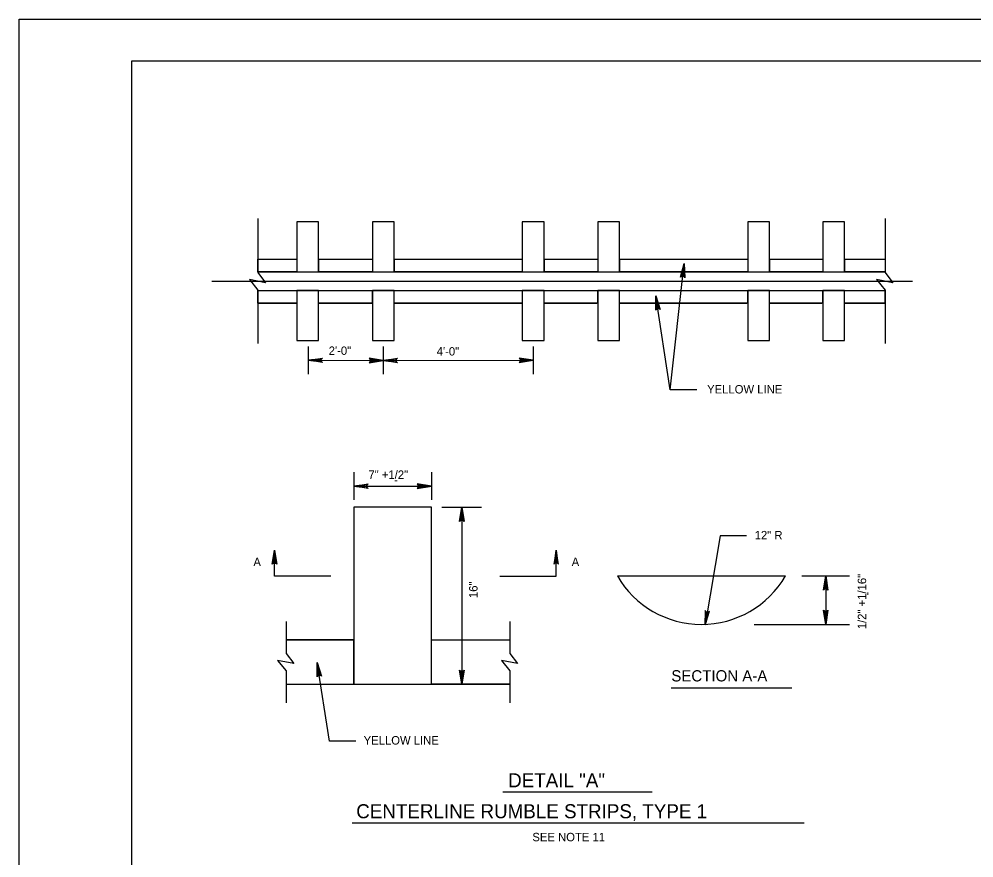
# Model space of a CAD drawing. Extents: x 632008 to 634206, y 294231 to 297795.
# Drawn here: x 632007.9 to 632347.6, y 297496.3 to 297794.6 of the extents above; entities that cross this region are included whole.
import ezdxf

# ---------------------------------------------------------------- set-up
doc = ezdxf.new("R2010")
doc.units = 0
for name, color, linetype in [('1', 7, 'Continuous'), ('Level 2', 7, 'Continuous'), ('PLT-BNDY', 7, 'Continuous')]:
    doc.layers.add(name, color=color, linetype=linetype)

msp = doc.modelspace()

# ---------------------------------------------------------------- linework, layer by layer
at = {"layer": '1'}
for p, q in [((632239.9, 297556.76), (632282.83, 297556.76)), ((632179.98, 297519.79), (632233.04, 297519.79)), ((632126.35, 297508.79), (632287.18, 297508.79))]:
    msp.add_line(p, q, dxfattribs=at)
msp.add_lwpolyline([(632833.86, 297215.62), (632833.86, 297779.62), (632047.86, 297779.62), (632047.86, 297215.62), (632833.86, 297215.62), (632833.86, 297241.98), (632633.86, 297241.98), (632633.86, 297306.66), (632833.86, 297306.66), (632833.86, 297335.62), (632633.86, 297335.62), (632633.86, 297215.62), (632712.66, 297215.62), (632712.66, 297241.98), (632712.66, 297215.62), (632789.66, 297215.62), (632789.66, 297241.98), (632789.66, 297229.66), (632833.86, 297229.66)], dxfattribs=at)
for points in [[(632092.79, 297709.21), (632106.62, 297709.21), (632106.62, 297704.76), (632092.79, 297704.76)], [(632114.46, 297709.21), (632133.54, 297709.21), (632133.54, 297704.76), (632114.46, 297704.76)], [(632141.38, 297709.21), (632186.9, 297709.21), (632186.9, 297704.76), (632141.38, 297704.76)], [(632194.74, 297709.21), (632213.73, 297709.21), (632213.73, 297704.76), (632194.74, 297704.76)], [(632221.57, 297709.21), (632267.09, 297709.21), (632267.09, 297704.76), (632221.57, 297704.76)], [(632274.93, 297709.21), (632293.77, 297709.21), (632293.77, 297704.76), (632274.93, 297704.76)], [(632301.61, 297709.21), (632315.97, 297709.21), (632315.97, 297704.76), (632301.61, 297704.76)], [(632092.79, 297698.09), (632106.62, 297698.09), (632106.62, 297693.64), (632092.79, 297693.64)], [(632114.41, 297698.09), (632133.49, 297698.09), (632133.49, 297693.63), (632114.41, 297693.63)], [(632141.33, 297698.08), (632186.85, 297698.08), (632186.85, 297693.63), (632141.33, 297693.63)], [(632194.69, 297698.08), (632213.68, 297698.08), (632213.68, 297693.63), (632194.69, 297693.63)], [(632221.51, 297698.08), (632267.04, 297698.08), (632267.04, 297693.63), (632221.51, 297693.63)], [(632274.88, 297698.08), (632293.72, 297698.08), (632293.72, 297693.63), (632274.88, 297693.63)], [(632301.56, 297698.08), (632315.92, 297698.08), (632315.92, 297693.63), (632301.56, 297693.63)], [(632127.01, 297573.83), (632102.86, 297573.83), (632102.86, 297569.06), (632105.61, 297565.4), (632099.85, 297566.52), (632102.86, 297562.8), (632102.86, 297558.09), (632127.01, 297558.09)], [(632154.55, 297573.83), (632182.49, 297573.83), (632182.5, 297569.06), (632185.24, 297565.4), (632179.48, 297566.52), (632182.49, 297562.8), (632182.49, 297558.09), (632154.55, 297558.09)]]:
    msp.add_lwpolyline(points, close=True, dxfattribs=at)
at = {"layer": 'Level 2'}
for p, q in [((632092.79, 297723.7), (632092.79, 297704.53)), ((632315.97, 297723.7), (632315.97, 297704.53)), ((632092.79, 297709.21), (632106.64, 297709.21)), ((632092.79, 297709.21), (632106.67, 297709.21)), ((632114.46, 297709.21), (632133.37, 297709.21)), ((632141.38, 297709.21), (632186.75, 297709.21)), ((632194.74, 297709.21), (632213.44, 297709.21)), ((632221.57, 297709.21), (632266.82, 297709.21)), ((632239.52, 297662.73), (632244.5, 297707.74)), ((632274.93, 297709.21), (632293.51, 297709.21)), ((632301.61, 297709.21), (632315.97, 297709.21)), ((632092.79, 297704.76), (632315.97, 297704.76)), ((632092.79, 297704.53), (632095.54, 297700.87)), ((632315.97, 297704.53), (632318.72, 297700.87)), ((632076.4, 297701.42), (632325.68, 297701.42)), ((632095.54, 297700.87), (632089.78, 297701.98)), ((632089.78, 297701.98), (632092.79, 297698.26)), ((632318.72, 297700.87), (632312.96, 297701.98)), ((632312.96, 297701.98), (632315.97, 297698.26)), ((632092.79, 297698.26), (632092.79, 297679.23)), ((632092.79, 297698.09), (632315.97, 297698.09)), ((632315.97, 297698.26), (632315.97, 297679.23)), ((632092.79, 297693.64), (632106.59, 297693.64)), ((632092.79, 297693.64), (632106.62, 297693.64)), ((632114.41, 297693.64), (632133.31, 297693.64)), ((632141.33, 297693.64), (632186.7, 297693.64)), ((632194.69, 297693.64), (632213.39, 297693.64)), ((632221.51, 297693.64), (632266.77, 297693.64)), ((632274.88, 297693.64), (632293.46, 297693.64)), ((632301.56, 297693.64), (632315.97, 297693.64)), ((632110.75, 297678.2), (632110.75, 297668.35)), ((632137.43, 297678.2), (632137.43, 297668.35)), ((632190.79, 297678.2), (632190.79, 297668.35)), ((632110.75, 297673.28), (632137.43, 297673.18)), ((632137.43, 297673.18), (632190.79, 297673.28)), ((632127.01, 297633.48), (632127.01, 297623.62)), ((632154.55, 297633.48), (632154.55, 297623.62)), ((632127.01, 297628.55), (632154.55, 297628.55)), ((632158.31, 297621.04), (632172.43, 297621.04)), ((632165.37, 297621.04), (632165.37, 297558.09)), ((632220.72, 297596.57), (632280.5, 297596.57)), ((632286.37, 297596.57), (632303.28, 297596.57)), ((632294.82, 297596.57), (632294.82, 297579.35)), ((632102.86, 297580.42), (632102.86, 297569.06)), ((632182.5, 297580.42), (632182.5, 297569.06)), ((632269.39, 297579.35), (632303.28, 297579.35)), ((632102.86, 297573.83), (632127.01, 297573.83)), ((632154.55, 297573.83), (632182.5, 297573.83)), ((632102.86, 297569.06), (632105.61, 297565.4)), ((632182.5, 297569.06), (632185.24, 297565.4)), ((632105.61, 297565.4), (632099.85, 297566.52)), ((632099.85, 297566.52), (632102.86, 297562.8)), ((632185.24, 297565.4), (632179.48, 297566.52)), ((632179.48, 297566.52), (632182.49, 297562.8)), ((632102.86, 297562.8), (632102.86, 297551.44)), ((632182.49, 297562.8), (632182.5, 297551.44)), ((632102.86, 297558.09), (632182.49, 297558.09))]:
    msp.add_line(p, q, dxfattribs=at)
for points in [[(632106.62, 297704.76), (632114.41, 297704.76), (632114.41, 297722.55), (632106.62, 297722.55)], [(632133.54, 297704.76), (632141.33, 297704.76), (632141.33, 297722.55), (632133.54, 297722.55)], [(632186.9, 297704.76), (632194.69, 297704.76), (632194.69, 297722.55), (632186.9, 297722.55)], [(632213.73, 297704.76), (632221.51, 297704.76), (632221.51, 297722.55), (632213.73, 297722.55)], [(632267.09, 297704.76), (632274.88, 297704.76), (632274.88, 297722.55), (632267.09, 297722.55)], [(632293.77, 297704.76), (632301.56, 297704.76), (632301.56, 297722.55), (632293.77, 297722.55)], [(632106.62, 297680.29), (632114.41, 297680.29), (632114.41, 297698.09), (632106.62, 297698.09)], [(632133.54, 297680.29), (632141.33, 297680.29), (632141.33, 297698.08), (632133.54, 297698.08)], [(632186.9, 297680.29), (632194.69, 297680.29), (632194.69, 297698.08), (632186.9, 297698.08)], [(632213.73, 297680.29), (632221.51, 297680.29), (632221.51, 297698.08), (632213.73, 297698.08)], [(632267.09, 297680.29), (632274.88, 297680.29), (632274.88, 297698.08), (632267.09, 297698.08)], [(632293.77, 297680.29), (632301.56, 297680.29), (632301.56, 297698.08), (632293.77, 297698.08)], [(632127.01, 297558.09), (632154.55, 297558.09), (632154.55, 297621.04), (632127.01, 297621.04)]]:
    msp.add_lwpolyline(points, close=True, dxfattribs=at)
for points in [[(632243.38, 297703.04), (632243.75, 297703.18), (632244.5, 297707.74), (632243.38, 297703.04), (632243.14, 297702.82), (632244.5, 297707.74), (632244.23, 297703.13), (632244.55, 297702.92), (632244.5, 297707.74), (632244.75, 297702.64), (632244.55, 297702.92)], [(632234.53, 297691.37), (632234.84, 297691.6), (632234.38, 297696.2), (632234.53, 297691.37), (632234.36, 297691.09), (632234.38, 297696.2), (632235.32, 297691.68), (632235.68, 297691.56), (632234.38, 297696.2), (632235.95, 297691.34), (632235.68, 297691.56)], [(632248.94, 297662.73), (632239.52, 297662.73), (632234.38, 297696.2)], [(632115.55, 297672.68), (632115.37, 297673.02), (632110.75, 297673.28), (632115.55, 297672.68), (632115.79, 297672.47), (632110.75, 297673.28), (632115.37, 297673.51), (632115.53, 297673.85), (632110.75, 297673.28), (632115.79, 297674.08), (632115.53, 297673.85)], [(632132.64, 297672.58), (632132.82, 297672.93), (632137.43, 297673.18), (632132.64, 297672.58), (632132.39, 297672.37), (632137.43, 297673.18), (632132.82, 297673.41), (632132.65, 297673.75), (632137.43, 297673.18), (632132.39, 297673.98), (632132.65, 297673.75)], [(632142.23, 297672.58), (632142.05, 297672.93), (632137.43, 297673.18), (632142.23, 297672.58), (632142.47, 297672.37), (632137.43, 297673.18), (632142.05, 297673.41), (632142.22, 297673.75), (632137.43, 297673.18), (632142.47, 297673.98), (632142.22, 297673.75)], [(632186, 297672.68), (632186.18, 297673.02), (632190.79, 297673.28), (632186, 297672.68), (632185.75, 297672.47), (632190.79, 297673.28), (632186.18, 297673.51), (632186.01, 297673.85), (632190.79, 297673.28), (632185.75, 297674.08), (632186.01, 297673.85)], [(632131.81, 297627.95), (632131.63, 297628.29), (632127.01, 297628.55), (632131.81, 297627.95), (632132.06, 297627.74), (632127.01, 297628.55), (632131.63, 297628.78), (632131.8, 297629.12), (632127.01, 297628.55), (632132.06, 297629.35), (632131.8, 297629.12)], [(632149.76, 297627.95), (632149.93, 297628.29), (632154.55, 297628.55), (632149.76, 297627.95), (632149.51, 297627.74), (632154.55, 297628.55), (632149.94, 297628.78), (632149.77, 297629.12), (632154.55, 297628.55), (632149.51, 297629.35), (632149.77, 297629.12)], [(632164.77, 297616.24), (632165.12, 297616.42), (632165.37, 297621.04), (632164.77, 297616.24), (632164.56, 297616), (632165.37, 297621.04), (632165.6, 297616.42), (632165.94, 297616.26), (632165.37, 297621.04), (632166.17, 297616), (632165.94, 297616.26)], [(632266.64, 297610.9), (632257.23, 297610.9), (632251.93, 297579.2)], [(632098.13, 297600.97), (632098.48, 297601.15), (632098.74, 297605.77), (632098.13, 297600.97), (632097.93, 297600.72), (632098.74, 297605.77), (632098.97, 297601.15), (632099.31, 297600.98), (632098.74, 297605.77), (632099.54, 297600.72), (632099.31, 297600.98)], [(632118.82, 297596.56), (632098.74, 297596.56), (632098.74, 297605.77)], [(632178.87, 297596.56), (632198.95, 297596.56), (632198.95, 297605.77)], [(632199.56, 297600.97), (632199.21, 297601.15), (632198.95, 297605.77), (632199.56, 297600.97), (632199.77, 297600.72), (632198.95, 297605.77), (632198.73, 297601.15), (632198.38, 297600.98), (632198.95, 297605.77), (632198.15, 297600.72), (632198.38, 297600.98)], [(632294.22, 297591.77), (632294.57, 297591.95), (632294.82, 297596.57), (632294.22, 297591.77), (632294.01, 297591.53), (632294.82, 297596.57), (632295.05, 297591.96), (632295.39, 297591.79), (632294.82, 297596.57), (632295.62, 297591.53), (632295.39, 297591.79)], [(632252.09, 297584.02), (632252.4, 297583.8), (632251.93, 297579.2), (632252.09, 297584.02), (632251.92, 297584.3), (632251.93, 297579.2), (632252.88, 297583.71), (632253.24, 297583.83), (632251.93, 297579.2), (632253.51, 297584.05), (632253.24, 297583.83)], [(632295.42, 297584.15), (632295.08, 297583.97), (632294.82, 297579.35), (632295.42, 297584.15), (632295.63, 297584.39), (632294.82, 297579.35), (632294.59, 297583.97), (632294.25, 297584.13), (632294.82, 297579.35), (632294.02, 297584.39), (632294.25, 297584.13)], [(632114.08, 297560.98), (632114.39, 297561.21), (632113.93, 297565.81), (632114.08, 297560.98), (632113.91, 297560.7), (632113.93, 297565.81), (632114.87, 297561.29), (632115.23, 297561.17), (632113.93, 297565.81), (632115.5, 297560.95), (632115.23, 297561.17)], [(632127.65, 297537.78), (632118.24, 297537.78), (632113.93, 297565.81)], [(632165.97, 297562.89), (632165.63, 297562.71), (632165.37, 297558.09), (632165.97, 297562.89), (632166.18, 297563.13), (632165.37, 297558.09), (632165.14, 297562.71), (632164.8, 297562.87), (632165.37, 297558.09), (632164.57, 297563.13), (632164.8, 297562.87)]]:
    msp.add_lwpolyline(points, dxfattribs=at)
msp.add_arc((632250.61, 297613.91), 34.56, 210.1174, 329.8826, dxfattribs=at)
at = {"layer": 'PLT-BNDY'}
msp.add_lwpolyline([(632007.86, 297794.62), (632848.86, 297794.62), (632848.86, 297200.62), (632007.86, 297200.62)], close=True, dxfattribs=at)

# ---------------------------------------------------------------- texts
at = {"layer": 'Level 2'}
for s, height, p in [('2\'-0"', 3, (632118.01, 297675.2)), ('4\'-0"', 3, (632156.43, 297674.96)), ('YELLOW LINE', 3, (632252.64, 297661.48)), ('7" +1/2"', 3, (632132.14, 297631.12)), ('-', 3, (632141.29, 297629.22)), ('12" R', 3, (632269.57, 297609.59)), ('A', 3, (632091.22, 297600.09)), ('A', 3, (632204.46, 297600.09)), ('SECTION A-A', 4, (632239.9, 297559.07)), ('YELLOW LINE', 3, (632130.44, 297536.63)), ('DETAIL "A"', 5, (632181.85, 297521.41)), ('CENTERLINE RUMBLE STRIPS, TYPE 1', 5, (632127.8, 297510.41)), ('SEE NOTE 11', 3, (632190.46, 297502.22))]:
    msp.add_text(s, height=height, dxfattribs=at).set_placement(p)
for s, p in [('16"', (632170.96, 297588.72)), ('1/2" +1/16"', (632309.23, 297577.64)), ('-', (632311, 297589.65))]:
    msp.add_text(s, height=3, rotation=90, dxfattribs=at).set_placement(p)

doc.saveas('drawing.dxf')
